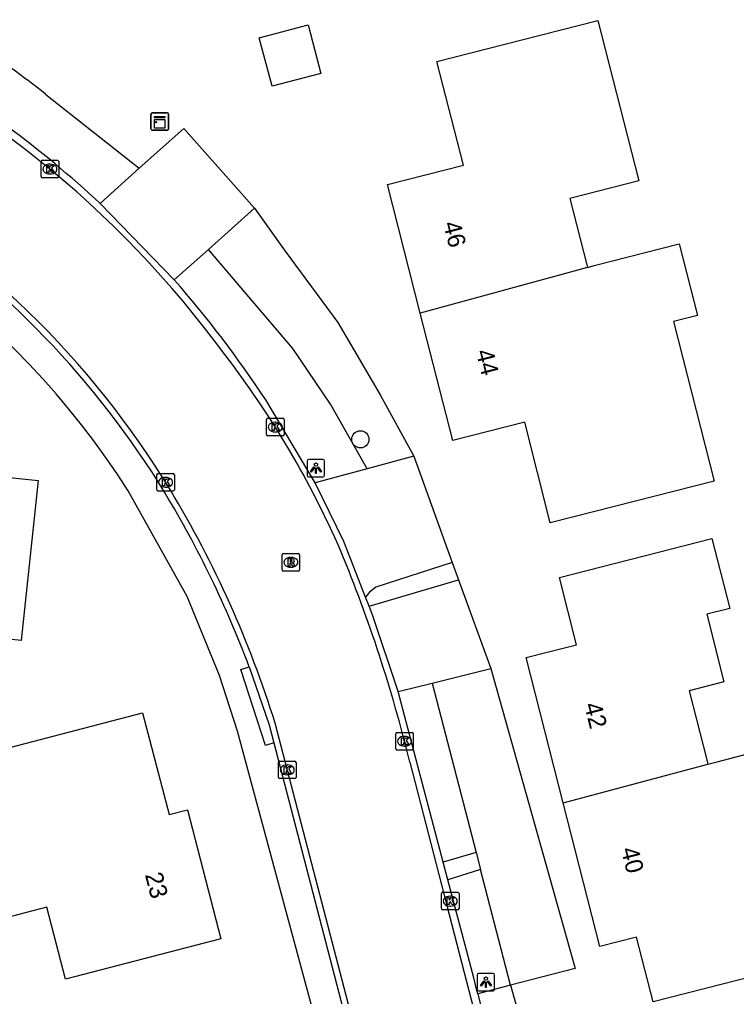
# Model space of a CAD drawing. Extents: x 162157 to 163165, y 378998 to 380775.
# Drawn here: x 162635.7 to 162676.5, y 380551.9 to 380607.6 of the extents above; entities that cross this region are included whole.
import ezdxf

# ---------------------------------------------------------------- set-up
doc = ezdxf.new("R2010")
doc.units = 0
for name, color, linetype in [('IMGEO_Berm_groen', 7, 'Continuous'), ('IMGEO_Boom', 7, 'Continuous'), ('IMGEO_Groenvoorziening', 7, 'Continuous'), ('IMGEO_Kast', 7, 'Continuous'), ('IMGEO_Kolk', 7, 'Continuous'), ('IMGEO_Lichtpunt', 7, 'Continuous'), ('IMGEO_Pand', 7, 'Continuous'), ('IMGEO_Pand_nummerreeks', 7, 'Continuous'), ('IMGEO_Rijbaan_lokaal_gesloten', 7, 'Continuous'), ('IMGEO_Rijbaan_lokaal_open', 7, 'Continuous'), ('IMGEO_Rioolput', 7, 'Continuous'), ('IMGEO_Voetpad_open', 7, 'Continuous')]:
    doc.layers.add(name, color=color, linetype=linetype)

msp = doc.modelspace()

# ---------------------------------------------------------------- linework, layer by layer
at = {"layer": 'IMGEO_Berm_groen'}
for points in [[(162637.173, 380603.295), (162642.5, 380599.088)], [(162655.474, 380581.988), (162653.394, 380585.655), (162651.242, 380588.825), (162646.436, 380594.472)]]:
    msp.add_lwpolyline(points, dxfattribs=at)
msp.add_arc((162610.535, 380570.327), 42.385, 51.0619, 64.4657, dxfattribs=at)
at = {"layer": 'IMGEO_Boom'}
msp.add_circle((162655.093, 380583.657), 0.489, dxfattribs=at)
at = {"layer": 'IMGEO_Groenvoorziening'}
for points in [[(162649.073, 380596.811), (162650.808, 380594.376), (162653.802, 380590.305), (162656.227, 380586.187), (162658.133, 380582.706)], [(162660.325, 380576.658), (162660.688, 380575.655)], [(162662.517, 380570.61), (162667.327, 380553.534), (162663.653, 380552.582)], [(162659.183, 380569.783), (162661.682, 380560.136)], [(162663.653, 380552.582), (162661.934, 380559.164)]]:
    msp.add_lwpolyline(points, dxfattribs=at)
at = {"layer": 'IMGEO_Kast'}
for p, q in [((162643.245, 380602.252), (162644.086, 380602.252)), ((162644.086, 380602.252), (162643.245, 380602.252)), ((162643.17, 380601.327), (162643.17, 380602.168)), ((162643.17, 380602.168), (162643.17, 380601.327)), ((162644.17, 380602.177), (162644.17, 380601.336)), ((162644.17, 380601.336), (162644.17, 380602.177)), ((162644.095, 380601.252), (162643.254, 380601.252)), ((162643.254, 380601.252), (162644.095, 380601.252))]:
    msp.add_line(p, q, dxfattribs=at)
for points in [[(162643.365, 380602.042), (162643.965, 380602.042), (162643.965, 380601.957), (162643.365, 380601.957), (162643.365, 380602.042)], [(162643.365, 380601.867), (162643.965, 380601.867), (162643.965, 380601.378), (162643.365, 380601.378), (162643.365, 380601.867)]]:
    msp.add_lwpolyline(points, dxfattribs=at)
msp.add_circle((162643.449, 380601.716), 0.0377, dxfattribs=at)
for centre, start, end in [((162643.248, 380602.174), 92.4484, 184.2845), ((162643.248, 380602.174), 92.4484, 184.2845), ((162644.092, 380602.174), 2.4484, 94.2845), ((162644.092, 380602.174), 2.4484, 94.2845), ((162643.248, 380601.33), 182.4484, 274.2845), ((162643.248, 380601.33), 182.4484, 274.2845), ((162644.092, 380601.33), 272.4484, 4.2845), ((162644.092, 380601.33), 272.4484, 4.2845)]:
    msp.add_arc(centre, 0.0779, start, end, dxfattribs=at)
at = {"layer": 'IMGEO_Kolk'}
for p, q in [((162636.912, 380598.618), (162636.912, 380599.47)), ((162636.987, 380599.544), (162637.839, 380599.544)), ((162637.913, 380599.47), (162637.913, 380598.618)), ((162637.4, 380599.324), (162637.425, 380599.324)), ((162637.839, 380598.544), (162636.987, 380598.544)), ((162637.423, 380598.764), (162637.398, 380598.764)), ((162649.749, 380583.931), (162649.749, 380584.783)), ((162649.824, 380584.857), (162650.676, 380584.857)), ((162650.237, 380584.637), (162650.262, 380584.637)), ((162650.75, 380584.783), (162650.75, 380583.931)), ((162650.26, 380584.077), (162650.235, 380584.077)), ((162650.676, 380583.857), (162649.824, 380583.857)), ((162643.575, 380581.716), (162644.427, 380581.716)), ((162643.5, 380580.79), (162643.5, 380581.642)), ((162643.988, 380581.496), (162644.013, 380581.496)), ((162644.501, 380581.642), (162644.501, 380580.79)), ((162644.427, 380580.716), (162643.575, 380580.716)), ((162644.011, 380580.936), (162643.986, 380580.936)), ((162657.109, 380566.047), (162657.109, 380566.899)), ((162657.184, 380566.973), (162658.036, 380566.973)), ((162657.597, 380566.753), (162657.622, 380566.753)), ((162658.11, 380566.899), (162658.11, 380566.047)), ((162657.62, 380566.193), (162657.595, 380566.193)), ((162658.036, 380565.973), (162657.184, 380565.973)), ((162650.428, 380564.419), (162650.428, 380565.271)), ((162650.503, 380565.345), (162651.355, 380565.345)), ((162650.916, 380565.125), (162650.941, 380565.125)), ((162651.429, 380565.271), (162651.429, 380564.419)), ((162650.939, 380564.565), (162650.914, 380564.565)), ((162651.355, 380564.345), (162650.503, 380564.345)), ((162659.711, 380556.947), (162659.711, 380557.799)), ((162659.786, 380557.873), (162660.638, 380557.873)), ((162660.712, 380557.799), (162660.712, 380556.947)), ((162660.199, 380557.653), (162660.224, 380557.653)), ((162660.638, 380556.873), (162659.786, 380556.873)), ((162660.222, 380557.093), (162660.197, 380557.093))]:
    msp.add_line(p, q, dxfattribs=at)
for points in [[(162636.912, 380598.618), (162636.912, 380599.47)], [(162636.987, 380599.544), (162637.839, 380599.544)], [(162637.913, 380599.47), (162637.913, 380598.618)], [(162637.233, 380599.244), (162637.356, 380599.244), (162637.356, 380599.093), (162637.486, 380599.244), (162637.65, 380599.244), (162637.504, 380599.093), (162637.657, 380598.844), (162637.505, 380598.844), (162637.42, 380599.008), (162637.356, 380598.941), (162637.356, 380598.844), (162637.233, 380598.844), (162637.233, 380599.244)], [(162637.839, 380598.544), (162636.987, 380598.544)], [(162649.749, 380583.931), (162649.749, 380584.783)], [(162649.824, 380584.857), (162650.676, 380584.857)], [(162650.07, 380584.557), (162650.193, 380584.557), (162650.193, 380584.406), (162650.323, 380584.557), (162650.487, 380584.557), (162650.341, 380584.406), (162650.494, 380584.157), (162650.342, 380584.157), (162650.257, 380584.321), (162650.193, 380584.254), (162650.193, 380584.157), (162650.07, 380584.157), (162650.07, 380584.557)], [(162650.75, 380584.783), (162650.75, 380583.931)], [(162650.676, 380583.857), (162649.824, 380583.857)], [(162643.575, 380581.716), (162644.427, 380581.716)], [(162643.5, 380580.79), (162643.5, 380581.642)], [(162643.821, 380581.416), (162643.944, 380581.416), (162643.944, 380581.265), (162644.074, 380581.416), (162644.238, 380581.416), (162644.092, 380581.265), (162644.245, 380581.016), (162644.093, 380581.016), (162644.008, 380581.18), (162643.944, 380581.113), (162643.944, 380581.016), (162643.821, 380581.016), (162643.821, 380581.416)], [(162644.501, 380581.642), (162644.501, 380580.79)], [(162644.427, 380580.716), (162643.575, 380580.716)], [(162657.109, 380566.047), (162657.109, 380566.899)], [(162657.184, 380566.973), (162658.036, 380566.973)], [(162657.43, 380566.673), (162657.553, 380566.673), (162657.553, 380566.522), (162657.683, 380566.673), (162657.847, 380566.673), (162657.701, 380566.522), (162657.854, 380566.273), (162657.702, 380566.273), (162657.617, 380566.437), (162657.553, 380566.37), (162657.553, 380566.273), (162657.43, 380566.273), (162657.43, 380566.673)], [(162658.11, 380566.899), (162658.11, 380566.047)], [(162658.036, 380565.973), (162657.184, 380565.973)], [(162650.428, 380564.419), (162650.428, 380565.271)], [(162650.503, 380565.345), (162651.355, 380565.345)], [(162650.749, 380565.045), (162650.872, 380565.045), (162650.872, 380564.894), (162651.002, 380565.045), (162651.166, 380565.045), (162651.02, 380564.894), (162651.173, 380564.645), (162651.021, 380564.645), (162650.936, 380564.809), (162650.872, 380564.742), (162650.872, 380564.645), (162650.749, 380564.645), (162650.749, 380565.045)], [(162651.429, 380565.271), (162651.429, 380564.419)], [(162651.355, 380564.345), (162650.503, 380564.345)], [(162659.711, 380556.947), (162659.711, 380557.799)], [(162659.786, 380557.873), (162660.638, 380557.873)], [(162660.712, 380557.799), (162660.712, 380556.947)], [(162660.032, 380557.573), (162660.155, 380557.573), (162660.155, 380557.422), (162660.285, 380557.573), (162660.449, 380557.573), (162660.303, 380557.422), (162660.456, 380557.173), (162660.304, 380557.173), (162660.219, 380557.337), (162660.155, 380557.27), (162660.155, 380557.173), (162660.032, 380557.173), (162660.032, 380557.573)], [(162660.638, 380556.873), (162659.786, 380556.873)]]:
    msp.add_lwpolyline(points, dxfattribs=at)
for centre, start, end in [((162636.989, 380599.468), 91.552, 178.448), ((162636.989, 380599.468), 91.552, 178.448), ((162637.837, 380599.468), 1.552, 88.448), ((162637.837, 380599.468), 1.552, 88.448), ((162636.989, 380598.62), 181.552, 268.448), ((162636.989, 380598.62), 181.552, 268.448), ((162637.837, 380598.62), 271.552, 358.448), ((162637.837, 380598.62), 271.552, 358.448), ((162649.826, 380584.781), 91.552, 178.448), ((162649.826, 380584.781), 91.552, 178.448), ((162650.674, 380584.781), 1.552, 88.448), ((162650.674, 380584.781), 1.552, 88.448), ((162649.826, 380583.933), 181.552, 268.448), ((162649.826, 380583.933), 181.552, 268.448), ((162650.674, 380583.933), 271.552, 358.448), ((162650.674, 380583.933), 271.552, 358.448), ((162643.577, 380581.64), 91.552, 178.448), ((162643.577, 380581.64), 91.552, 178.448), ((162644.425, 380581.64), 1.552, 88.448), ((162644.425, 380581.64), 1.552, 88.448), ((162643.577, 380580.792), 181.552, 268.448), ((162643.577, 380580.792), 181.552, 268.448), ((162644.425, 380580.792), 271.552, 358.448), ((162644.425, 380580.792), 271.552, 358.448), ((162657.186, 380566.897), 91.552, 178.448), ((162657.186, 380566.897), 91.552, 178.448), ((162658.034, 380566.897), 1.552, 88.448), ((162658.034, 380566.897), 1.552, 88.448), ((162657.186, 380566.049), 181.552, 268.448), ((162657.186, 380566.049), 181.552, 268.448), ((162658.034, 380566.049), 271.552, 358.448), ((162658.034, 380566.049), 271.552, 358.448), ((162650.505, 380565.269), 91.552, 178.448), ((162650.505, 380565.269), 91.552, 178.448), ((162651.353, 380565.269), 1.552, 88.448), ((162651.353, 380565.269), 1.552, 88.448), ((162650.505, 380564.421), 181.552, 268.448), ((162650.505, 380564.421), 181.552, 268.448), ((162651.353, 380564.421), 271.552, 358.448), ((162651.353, 380564.421), 271.552, 358.448), ((162659.788, 380557.797), 91.552, 178.448), ((162659.788, 380557.797), 91.552, 178.448), ((162660.636, 380557.797), 1.552, 88.448), ((162660.636, 380557.797), 1.552, 88.448), ((162659.788, 380556.949), 181.552, 268.448), ((162659.788, 380556.949), 181.552, 268.448), ((162660.636, 380556.949), 271.552, 358.448), ((162660.636, 380556.949), 271.552, 358.448)]:
    msp.add_arc(centre, 0.0765, start, end, dxfattribs=at)
for centre, major_axis, ratio, start_param, end_param in [((162637.399, 380599.044), (-0.387, 0.002), 0.722429, 4.712389, 7.853982), ((162637.424, 380599.044), (-0.39, 0.002), 0.717154, 1.570796, 4.712389), ((162650.236, 380584.357), (-0.387, 0.002), 0.722429, 4.712389, 7.853982), ((162650.261, 380584.357), (-0.39, 0.002), 0.717154, 1.570796, 4.712389), ((162643.987, 380581.216), (-0.387, 0.002), 0.722429, 4.712389, 7.853982), ((162644.012, 380581.216), (-0.39, 0.002), 0.717154, 1.570796, 4.712389), ((162657.596, 380566.473), (-0.387, 0.002), 0.722429, 4.712389, 7.853982), ((162657.621, 380566.473), (-0.39, 0.002), 0.717154, 1.570796, 4.712389), ((162650.915, 380564.845), (-0.387, 0.002), 0.722429, 4.712389, 7.853982), ((162650.94, 380564.845), (-0.39, 0.002), 0.717154, 1.570796, 4.712389), ((162660.198, 380557.373), (-0.387, 0.002), 0.722429, 4.712389, 7.853982), ((162660.223, 380557.373), (-0.39, 0.002), 0.717154, 1.570796, 4.712389)]:
    msp.add_ellipse(centre, major_axis=major_axis, ratio=ratio, start_param=start_param, end_param=end_param, dxfattribs=at)
at = {"layer": 'IMGEO_Lichtpunt'}
for p, q in [((162652.063, 380582.425), (162652.063, 380581.618)), ((162652.063, 380582.425), (162652.063, 380581.618)), ((162652.965, 380582.52), (162652.157, 380582.52)), ((162652.965, 380582.52), (162652.157, 380582.52)), ((162653.059, 380581.618), (162653.059, 380582.425)), ((162653.059, 380581.618), (162653.059, 380582.425)), ((162652.157, 380581.524), (162652.965, 380581.524)), ((162652.157, 380581.524), (162652.965, 380581.524)), ((162661.744, 380553.166), (162661.744, 380552.359)), ((162661.744, 380553.166), (162661.744, 380552.359)), ((162662.646, 380553.261), (162661.838, 380553.261)), ((162662.646, 380553.261), (162661.838, 380553.261)), ((162662.74, 380552.359), (162662.74, 380553.166)), ((162662.74, 380552.359), (162662.74, 380553.166)), ((162661.838, 380552.265), (162662.646, 380552.265)), ((162661.838, 380552.265), (162662.646, 380552.265))]:
    msp.add_line(p, q, dxfattribs=at)
for points in [[(162652.437, 380582.089), (162652.476, 380582.061), (162652.288, 380581.799), (162652.25, 380581.826), (162652.437, 380582.089)], [(162652.539, 380582.041), (162652.586, 380582.041), (162652.586, 380581.719), (162652.539, 380581.719), (162652.539, 380582.041)], [(162652.649, 380582.061), (162652.687, 380582.088), (162652.874, 380581.826), (162652.835, 380581.798), (162652.649, 380582.061)], [(162662.118, 380552.83), (162662.157, 380552.802), (162661.969, 380552.54), (162661.931, 380552.567), (162662.118, 380552.83)], [(162662.22, 380552.782), (162662.267, 380552.782), (162662.267, 380552.46), (162662.22, 380552.46), (162662.22, 380552.782)], [(162662.33, 380552.802), (162662.368, 380552.829), (162662.555, 380552.567), (162662.516, 380552.539), (162662.33, 380552.802)]]:
    msp.add_lwpolyline(points, dxfattribs=at)
for centre in [(162652.562, 380582.223), (162662.243, 380552.964)]:
    msp.add_circle(centre, 0.0994, dxfattribs=at)
for centre, start, end in [((162652.157, 380582.425), 90, 180), ((162652.157, 380582.425), 90, 180), ((162652.965, 380582.425), 0, 90), ((162652.965, 380582.425), 0, 90), ((162652.157, 380581.618), 180, 270), ((162652.157, 380581.618), 180, 270), ((162652.965, 380581.618), 270, 0), ((162652.965, 380581.618), 270, 360), ((162661.838, 380553.166), 90, 180), ((162661.838, 380553.166), 90, 180), ((162662.646, 380553.166), 0, 90), ((162662.646, 380553.166), 0, 90), ((162661.838, 380552.359), 180, 270), ((162661.838, 380552.359), 180, 270), ((162662.646, 380552.359), 270, 0), ((162662.646, 380552.359), 270, 360)]:
    msp.add_arc(centre, 0.0946, start, end, dxfattribs=at)
at = {"layer": 'IMGEO_Pand'}
for points in [[(162650.064, 380603.755), (162649.332, 380606.517), (162652.116, 380607.255), (162652.848, 380604.492), (162650.064, 380603.755)], [(162658.502, 380590.837), (162656.633, 380598.161), (162660.962, 380599.265), (162659.457, 380605.165), (162664.282, 380606.396), (162668.623, 380607.503), (162670.951, 380598.375), (162667.02, 380597.372), (162667.984, 380593.59), (162668.02, 380593.45)], [(162668.02, 380593.45), (162668.41, 380593.557), (162673.246, 380594.791), (162674.286, 380590.711), (162672.919, 380590.362), (162675.234, 380581.284), (162670.756, 380580.141), (162665.911, 380578.905), (162664.451, 380584.63), (162660.352, 380583.585), (162658.502, 380590.837)], [(162668.02, 380593.45), (162658.502, 380590.837)], [(162623.079, 380581.654), (162629.092, 380581.017), (162629.208, 380582.117), (162636.747, 380581.318), (162635.782, 380572.214), (162628.507, 380572.985), (162628.304, 380571.067), (162622.027, 380571.733), (162623.079, 380581.654)], [(162666.65, 380562.964), (162664.54, 380571.238), (162665.652, 380571.522), (162667.402, 380571.968), (162666.426, 380575.791), (162671.251, 380577.022), (162675.114, 380578.007), (162676.126, 380574.039), (162674.819, 380573.705), (162675.802, 380569.851), (162673.825, 380569.347), (162674.827, 380565.421), (162674.891, 380565.17)], [(162629.574, 380551.985), (162630.895, 380565.021), (162633.011, 380565.571), (162642.693, 380568.089), (162644.2, 380562.299), (162645.247, 380562.572), (162647.155, 380555.235), (162638.31, 380552.933), (162637.247, 380557.021), (162633.523, 380556.053), (162634.361, 380552.832), (162633.161, 380552.52)], [(162674.891, 380565.17), (162675.412, 380565.31), (162678.155, 380566.022), (162678.193, 380565.875), (162679.111, 380562.278), (162679.945, 380562.491), (162681.067, 380558.092), (162680.234, 380557.879), (162681.213, 380554.042), (162676.612, 380552.868), (162671.767, 380551.632), (162670.826, 380555.319), (162668.736, 380554.785), (162666.65, 380562.964)], [(162666.65, 380562.964), (162674.891, 380565.17)]]:
    msp.add_lwpolyline(points, dxfattribs=at)
at = {"layer": 'IMGEO_Rijbaan_lokaal_gesloten'}
for points in [[(162648.766, 380570.704), (162649.9, 380567.405), (162650.166, 380566.381)], [(162657.649, 380539.117), (162650.238, 380567.497)], [(162650.166, 380566.381), (162655.824, 380544.641)], [(162657.91, 380565.281), (162660.014, 380557.121), (162667.731, 380527.348), (162674.932, 380500), (162681.65, 380474.495), (162683.015, 380468.663), (162684.023, 380462.108), (162684.831, 380454.251), (162685.204, 380450.618)]]:
    msp.add_lwpolyline(points, dxfattribs=at)
for centre, radius, start, end in [((162600.336, 380554.092), 58.268, 36.18143, 66.51187), ((162600.412, 380554.071), 51.351, 31.3235, 60.387), ((162600.349, 380554.01), 51.087, 31.347, 56.6074), ((162605.343, 380556.113), 53.05, 23.5221, 37.6126), ((162592.135, 380549.372), 60.515, 20.64102, 31.05157), ((162592.506, 380549.545), 60.458, 17.27331, 31.09239), ((162577.264, 380545.555), 83.024, 13.74434, 22.4685)]:
    msp.add_arc(centre, radius, start, end, dxfattribs=at)
at = {"layer": 'IMGEO_Rijbaan_lokaal_open'}
for points in [[(162644.491, 380592.747), (162640.268, 380597.09)], [(162652.518, 380581.189), (162649.703, 380585.899)], [(162655.391, 380574.679), (162654.146, 380577.85), (162652.518, 380581.189)], [(162655.594, 380574.162), (162655.391, 380574.679)], [(162657.241, 380569.302), (162655.807, 380573.618), (162655.594, 380574.162)], [(162659.806, 380559.599), (162657.241, 380569.302)], [(162660.073, 380558.59), (162659.806, 380559.599)], [(162661.78, 380552.096), (162661.714, 380552.355), (162661.548, 380553.007), (162660.073, 380558.59)], [(162661.78, 380552.096), (162661.941, 380551.466)]]:
    msp.add_lwpolyline(points, dxfattribs=at)
for centre, radius, start, end in [((162598.916, 380552.638), 60.712, 47.06893, 60.00871), ((162599.137, 380552.821), 60.424, 33.19108, 41.35831)]:
    msp.add_arc(centre, radius, start, end, dxfattribs=at)
at = {"layer": 'IMGEO_Rioolput'}
for p, q in [((162650.635, 380576.232), (162650.635, 380577.084)), ((162650.71, 380577.158), (162651.562, 380577.158)), ((162651.123, 380576.938), (162651.148, 380576.938)), ((162651.636, 380577.084), (162651.636, 380576.232)), ((162651.562, 380576.158), (162650.71, 380576.158)), ((162651.146, 380576.378), (162651.121, 380576.378))]:
    msp.add_line(p, q, dxfattribs=at)
for points in [[(162650.635, 380576.232), (162650.635, 380577.084)], [(162650.71, 380577.158), (162651.562, 380577.158)], [(162651.224, 380576.856), (162650.972, 380576.858), (162650.972, 380576.458)], [(162651.15, 380576.777), (162651.096, 380576.777), (162651.096, 380576.696)], [(162651.096, 380576.696), (162651.148, 380576.696)], [(162651.636, 380577.084), (162651.636, 380576.232)], [(162651.562, 380576.158), (162650.71, 380576.158)], [(162650.972, 380576.458), (162651.096, 380576.458), (162651.096, 380576.62), (162651.107, 380576.62)], [(162651.154, 380576.591), (162651.225, 380576.458), (162651.365, 380576.458), (162651.3, 380576.584)]]:
    msp.add_lwpolyline(points, dxfattribs=at)
for centre, radius, start, end in [((162650.712, 380577.082), 0.0765, 91.552, 178.448), ((162650.712, 380577.082), 0.0765, 91.552, 178.448), ((162651.132, 380576.885), 0.19, 274.7715, 282.9687), ((162651.156, 380576.681), 0.0964, 77.0061, 93.1865), ((162651.17, 380576.738), 0.0378, 276.6634, 79.6772), ((162651.223, 380576.746), 0.109, 350.3612, 89.416), ((162651.221, 380576.746), 0.112, 277.5842, 350.9817), ((162651.56, 380577.082), 0.0765, 1.552, 88.448), ((162651.56, 380577.082), 0.0765, 1.552, 88.448), ((162650.712, 380576.234), 0.0765, 181.552, 268.448), ((162650.712, 380576.234), 0.0765, 181.552, 268.448), ((162651.106, 380576.567), 0.0533, 26.0293, 88.6989), ((162651.205, 380576.531), 0.108, 29.5134, 73.7905), ((162651.56, 380576.234), 0.0765, 271.552, 358.448), ((162651.56, 380576.234), 0.0765, 271.552, 358.448)]:
    msp.add_arc(centre, radius, start, end, dxfattribs=at)
for centre, major_axis, ratio, start_param, end_param in [((162651.122, 380576.658), (-0.387, 0.002), 0.722429, 4.712389, 7.853982), ((162651.147, 380576.658), (-0.39, 0.002), 0.717154, 1.570796, 4.712389)]:
    msp.add_ellipse(centre, major_axis=major_axis, ratio=ratio, start_param=start_param, end_param=end_param, dxfattribs=at)
at = {"layer": 'IMGEO_Voetpad_open'}
for points in [[(162642.5, 380599.088), (162645.033, 380601.356), (162649.073, 380596.811)], [(162640.268, 380597.09), (162642.5, 380599.088)], [(162646.436, 380594.472), (162649.073, 380596.811)], [(162646.436, 380594.472), (162644.491, 380592.747)], [(162658.133, 380582.706), (162655.474, 380581.988)], [(162658.133, 380582.706), (162660.325, 380576.658)], [(162655.474, 380581.988), (162652.518, 380581.189)], [(162654.148, 380544.616), (162648.088, 380567.05), (162647.078, 380570.219), (162645.238, 380574.709), (162641.879, 380580.728)], [(162660.325, 380576.658), (162655.966, 380575.242), (162655.618, 380574.96), (162655.391, 380574.679)], [(162655.594, 380574.162), (162660.688, 380575.655)], [(162660.688, 380575.655), (162662.517, 380570.61)], [(162650.166, 380566.381), (162649.691, 380566.227), (162648.292, 380570.551), (162648.766, 380570.704)], [(162659.183, 380569.783), (162662.517, 380570.61)], [(162657.241, 380569.302), (162659.183, 380569.783)], [(162661.682, 380560.136), (162659.806, 380559.599)], [(162661.682, 380560.136), (162661.934, 380559.164)], [(162661.934, 380559.164), (162660.073, 380558.59)], [(162663.653, 380552.582), (162661.78, 380552.096)], [(162663.653, 380552.582), (162663.926, 380551.586), (162664.002, 380551.31), (162665.03, 380547.56), (162664.729, 380547.475), (162668.276, 380533.465), (162677.031, 380500), (162683.958, 380473.523)]]:
    msp.add_lwpolyline(points, dxfattribs=at)
msp.add_arc((162600.441, 380554.108), 49.251, 32.7166, 75.2098, dxfattribs=at)

# ---------------------------------------------------------------- texts
at = {"layer": 'IMGEO_Pand_nummerreeks'}
for s, rotation, p in [('46', 284.3123, (162659.801, 380595.941)), ('44', 284.3123, (162661.66, 380588.653)), ('42', 284.3065, (162667.826, 380568.551)), ('40', 284.3065, (162669.925, 380560.319)), ('23', 284.5758, (162642.818, 380558.879))]:
    msp.add_text(s, height=1, rotation=rotation, dxfattribs=at).set_placement(p)

doc.saveas('drawing.dxf')
